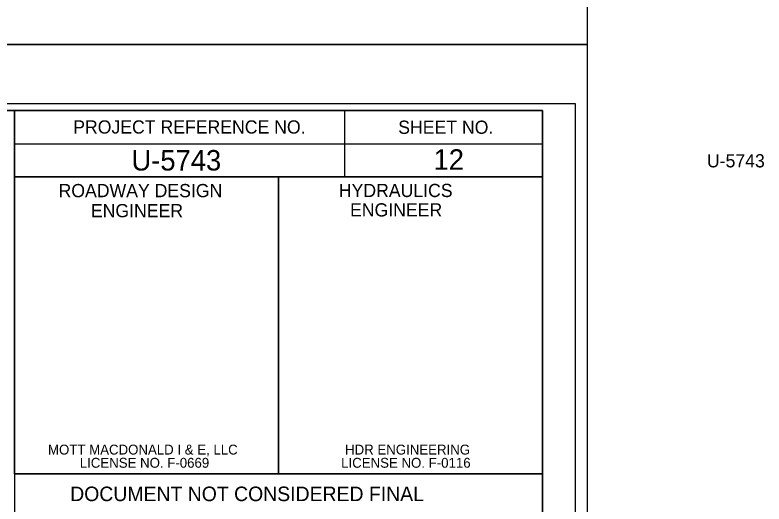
# Model space of a CAD drawing. Extents: x 1755181 to 1757273, y 729911 to 735411.
# Drawn here: x 1756647.8 to 1756931.6, y 730836.8 to 731022 of the extents above; entities that cross this region are included whole.
import ezdxf

# ---------------------------------------------------------------- set-up
doc = ezdxf.new("R2010")
doc.units = 0
for name, color, linetype in [('Old_Level_3', 7, 'Continuous'), ('Old_Level_45', 7, 'Continuous'), ('Sheet Cutting Line CELL', 7, 'Continuous'), ('Sheet Data Field CELL', 7, 'Continuous'), ('Sheet Plot Border Inside CELL', 7, 'Continuous'), ('Sheet Plot Border Outside CELL', 7, 'Continuous'), ('Sheet Profile CELL', 7, 'Continuous'), ('Sheet Profile Grid Major CELL', 7, 'Continuous'), ('Sheet Profile Grid Minor CELL', 7, 'Continuous'), ('Sheet Sticker Exception Certification CELL', 7, 'Continuous')]:
    doc.layers.add(name, color=color, linetype=linetype)

msp = doc.modelspace()

# ---------------------------------------------------------------- linework, layer by layer
at = {"layer": 'Sheet Cutting Line CELL'}
msp.add_line((1755180.67, 731010.78), (1756864.67, 731010.78), dxfattribs=at)
at = {"layer": 'Sheet Plot Border Inside CELL'}
msp.add_lwpolyline([(1755193.67, 729933.23), (1756860.17, 729933.23), (1756860.17, 730988.33), (1755193.67, 730988.33)], close=True, dxfattribs=at)
at = {"layer": 'Sheet Plot Border Outside CELL'}
for points in [[(1755180.67, 731010.78), (1756864.67, 731010.78), (1756864.67, 732110.78), (1755180.67, 732110.78)], [(1755180.67, 729910.78), (1756864.67, 729910.78), (1756864.67, 731010.78), (1755180.67, 731010.78)]]:
    msp.add_lwpolyline(points, close=True, dxfattribs=at)
at = {"layer": 'Sheet Profile CELL'}
for p, q in [((1756772.67, 730985.73), (1756772.67, 730960.73)), ((1756647.62, 730973.23), (1756847.67, 730973.23)), ((1756747.67, 730960.73), (1756747.67, 730848.28))]:
    msp.add_line(p, q, dxfattribs=at)
for points in [[(1756847.67, 730985.78), (1755347.67, 730985.78), (1755347.67, 729935.78), (1756847.67, 729935.78)], [(1756647.62, 730985.78), (1756847.67, 730985.78), (1756847.67, 730960.73), (1756647.62, 730960.73)], [(1756647.62, 730960.73), (1756747.67, 730960.73), (1756747.67, 730848.23), (1756647.62, 730848.23)], [(1756747.67, 730960.73), (1756847.67, 730960.73), (1756847.67, 730848.23), (1756747.67, 730848.23)]]:
    msp.add_lwpolyline(points, close=True, dxfattribs=at)
at = {"layer": 'Sheet Profile Grid Major CELL'}
msp.add_lwpolyline([(1756097.67, 730485.78), (1756147.67, 730485.78), (1756147.67, 730985.78), (1756197.67, 730985.78), (1756197.67, 730485.78), (1756247.67, 730485.78), (1756247.67, 730985.78), (1756297.67, 730985.78), (1756297.67, 730485.78), (1756347.67, 730485.78), (1756347.67, 730985.78), (1756397.67, 730985.78), (1756397.67, 730485.78), (1756447.67, 730485.78), (1756447.67, 730985.78), (1756497.67, 730985.78), (1756497.67, 730485.78), (1756547.67, 730485.78), (1756547.67, 730985.78), (1756597.67, 730985.78), (1756597.67, 730485.78), (1756647.67, 730485.78), (1756647.67, 730985.78), (1756673.97, 730985.78)], dxfattribs=at)
at = {"layer": 'Sheet Profile Grid Minor CELL'}
msp.add_lwpolyline([(1756642.67, 730985.78), (1756652.67, 730985.78)], dxfattribs=at)
at = {"layer": 'Sheet Sticker Exception Certification CELL'}
for p, q in [((1756647.62, 730848.23), (1756847.66, 730848.23)), ((1756847.66, 730848.22), (1756847.66, 730824.72))]:
    msp.add_line(p, q, dxfattribs=at)

# ---------------------------------------------------------------- texts
at = {"layer": 'Old_Level_3'}
for s, p in [('HDR ENGINEERING', (1756772.84, 730855.53)), (' LICENSE NO. F-0116', (1756769.97, 730850.53))]:
    msp.add_text(s, height=3.75, rotation=360, dxfattribs=at).set_placement(p)
at = {"layer": 'Old_Level_45'}
for s, p in [('MOTT MACDONALD I & E, LLC', (1756660.28, 730855.53)), (' LICENSE NO. F-0669', (1756670.92, 730850.53))]:
    msp.add_text(s, height=3.75, rotation=360, dxfattribs=at).set_placement(p)
at = {"layer": 'Sheet Data Field CELL'}
for s, p in [('U-5743', (1756691.91, 730963.1)), ('12', (1756806.37, 730963.4))]:
    msp.add_text(s, height=7.75, dxfattribs=at).set_placement(p)
at = {"layer": 'Sheet Profile CELL'}
for s, height, p in [('PROJECT REFERENCE NO.', 5.0001, (1756669.83, 730977.1)), ('SHEET NO.', 5, (1756792.98, 730977)), ('U-5743', 5, (1756909.95, 730964.29)), ('ROADWAY DESIGN', 5.0001, (1756664.28, 730953)), ('HYDRAULICS', 5, (1756770.48, 730953.05)), ('ENGINEER', 5, (1756676.53, 730945.4)), ('ENGINEER', 5, (1756774.73, 730945.7))]:
    msp.add_text(s, height=height, dxfattribs=at).set_placement(p)
at = {"layer": 'Sheet Sticker Exception Certification CELL'}
msp.add_text('DOCUMENT NOT CONSIDERED FINAL', height=5.5, dxfattribs=at).set_placement((1756668.69, 730837.89))

doc.saveas('drawing.dxf')
